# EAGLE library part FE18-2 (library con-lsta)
FEMALE HEADER
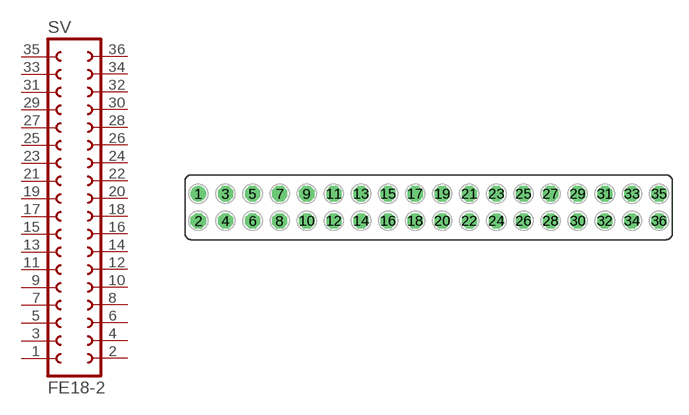
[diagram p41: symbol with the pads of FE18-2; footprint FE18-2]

Designator prefix SV

## FE18-2 (OC_FARNELL: unknown; OC_NEWARK: unknown)  [FE18-2]
1  1  pas
2  2  pas
3  3  pas
4  4  pas
5  5  pas
6  6  pas
7  7  pas
8  8  pas
9  9  pas
10  10  pas
11  11  pas
12  12  pas
13  13  pas
14  14  pas
15  15  pas
16  16  pas
17  17  pas
18  18  pas
19  19  pas
20  20  pas
21  21  pas
22  22  pas
23  23  pas
24  24  pas
25  25  pas
26  26  pas
27  27  pas
28  28  pas
29  29  pas
30  30  pas
31  31  pas
32  32  pas
33  33  pas
34  34  pas
35  35  pas
36  36  pas

## Footprint FE18-2 (pad centres in mm)
FEMALE HEADER
drill 0.914 round: 1 -21.59,1.27
drill 0.914 octagon: 2 -21.59,-1.27; 3 -19.05,1.27; 4 -19.05,-1.27; 5 -16.51,1.27; 6 -16.51,-1.27; 7 -13.97,1.27; 8 -13.97,-1.27; 9 -11.43,1.27; 10 -11.43,-1.27; 11 -8.89,1.27; 12 -8.89,-1.27; 13 -6.35,1.27; 14 -6.35,-1.27; 15 -3.81,1.27; 16 -3.81,-1.27; 17 -1.27,1.27; 18 -1.27,-1.27; 19 1.27,1.27; 20 1.27,-1.27; 21 3.81,1.27; 22 3.81,-1.27; 23 6.35,1.27; 24 6.35,-1.27; 25 8.89,1.27; 26 8.89,-1.27; 27 11.43,1.27; 28 11.43,-1.27; 29 13.97,1.27; 30 13.97,-1.27; 31 16.51,1.27; 32 16.51,-1.27; 33 19.05,1.27; 34 19.05,-1.27; 35 21.59,1.27; 36 21.59,-1.27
